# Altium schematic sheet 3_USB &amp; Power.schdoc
size 309 x 223 mm; Symbol: Sheet-Symbol_A4; Device: Sheet-Symbol_A4; Company: EasyEDA.com; Drawed: EasyEDA Pro; Reviewed: EasyEDA Pro; Version: V0.1; Page Size: A4; @Project Name: Recovery-Board-Kaveet-Saksham-Edition; @Page Count: 3; @Update Date: 2023-08-21; @Create Date: 2023-08-02; @Schematic Name: Schematic; Part Number: JLCPCB-002; @Page No: 3; @Page Name: USB &amp; Power
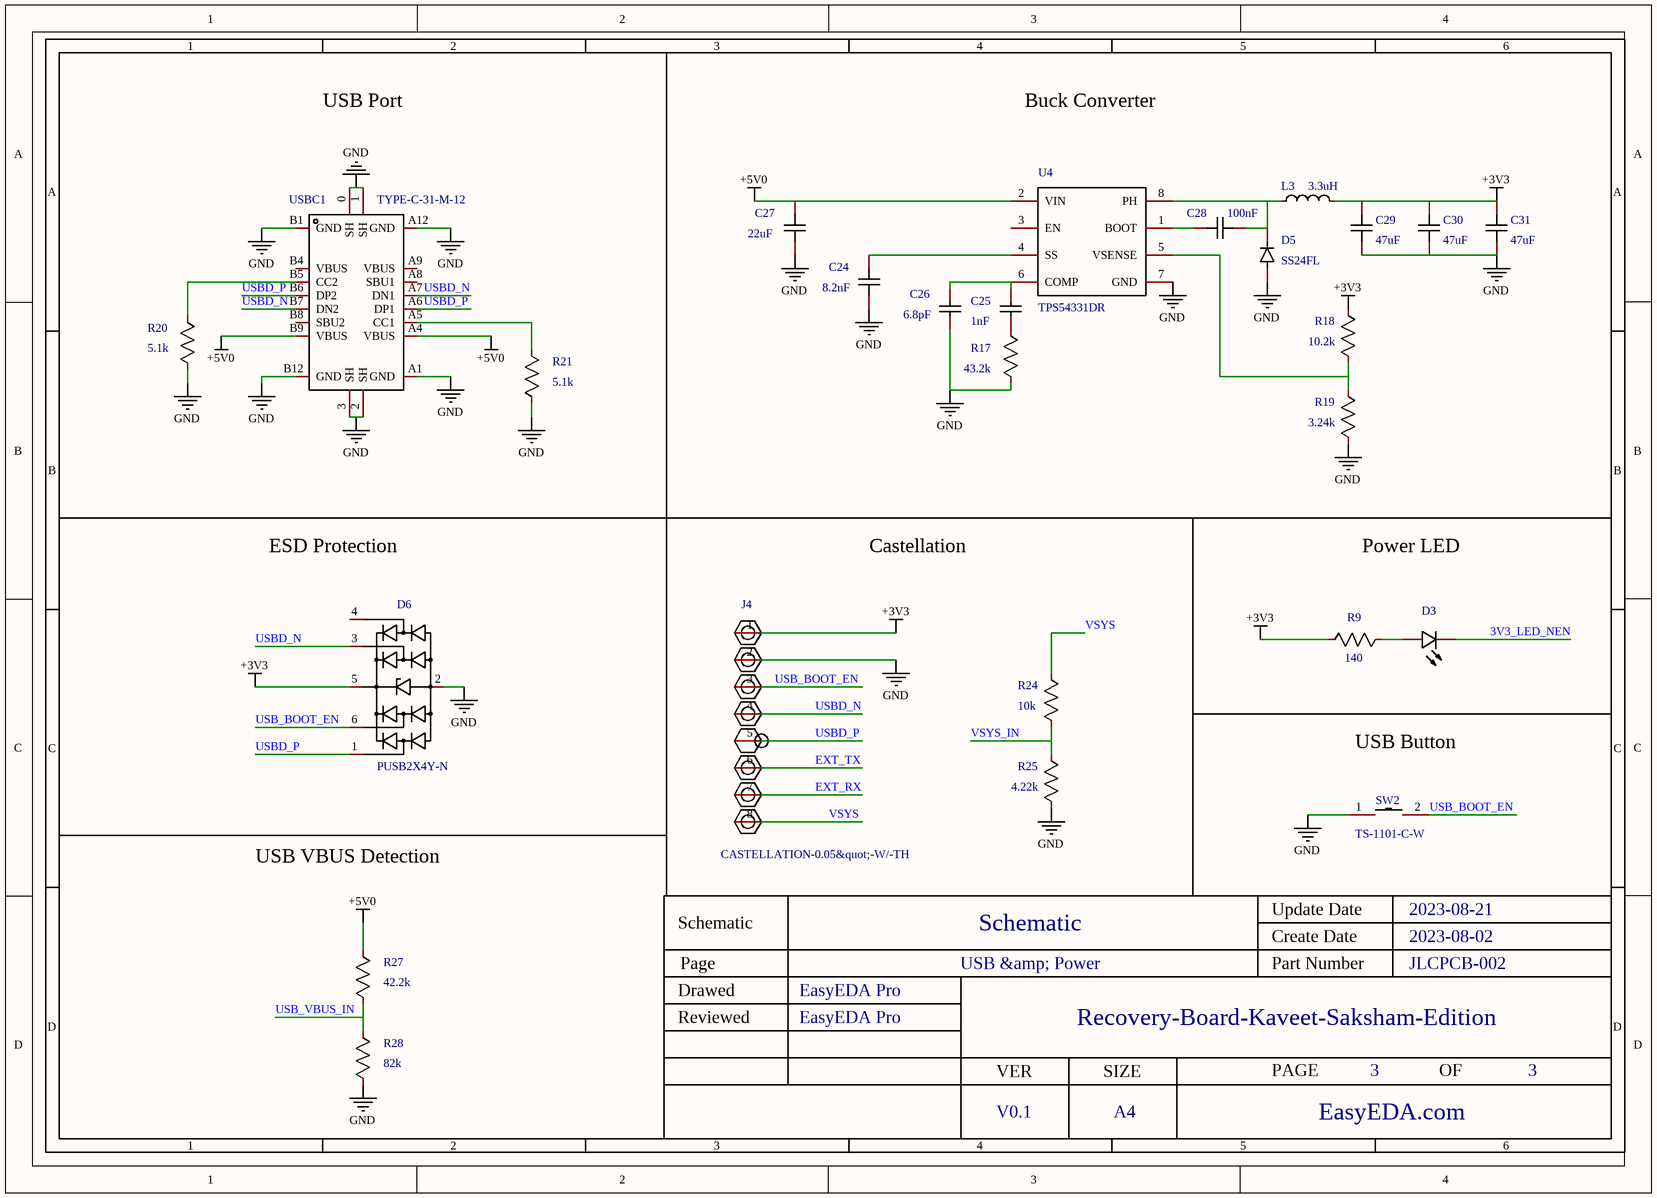
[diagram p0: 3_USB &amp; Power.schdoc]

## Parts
C24  8.2nF  [C0603]
C25  1nF  [C0402]
C26  6.8pF  [C0603]
C27  22uF  [C1210]
C28  100nF  [C0402]
C29  47uF  [C1206]
C30  47uF  [C1206]
C31  47uF  [C1206]
D3  16-213/SDRC/S530-A3/TR8  (value not drawn)
D5  SS24FL  [SODFL3617X108N]
D6  PUSB2X4Y-N  [SOT-363_L2.1-W1.3-P0.65-LS2.3-BL]
J4  CASTELLATION-0.05&quot;-W/-TH  [CASTELLATION-0.05"-W/-TH]
L3  3.3uH  [IND-SMD_L7.3-W6.6]
R9  140
R17  43.2k
R18  10.2k
R19  3.24k
R20  5.1k
R21  5.1k
R24  10k
R25  4.22k
R27  42.2k
R28  82k
SW2  TS-1101-C-W  [SW-SMD_L6.0-W3.3-LS8.0]
U4  TPS54331DR  [SOIC-8_L5.0-W4.0-P1.27-LS6.0-BL]
USBC1  TYPE-C-31-M-12  [USB-C_SMD-TYPE-C-31-M-12]

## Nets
+3V3: C29.2 C30.2 C31.2 D6.5(VCC) J4.1 L3.2 R9.1 R18.2
+5V0: C27.2 R27.2 U4.2(VIN) USBC1.A4(VBUS) USBC1.B9(VBUS)
GND: C24.1 C26.1 C27.1 C29.1 C30.1 C31.1 D5.A D6.2(GND) J4.2 R17.1 R19.1 R20.1 R21.1 R25.1 R28.1 SW2.1 U4.7(GND) USBC1.0(SH) USBC1.1(SH) USBC1.2(SH) USBC1.3(SH) USBC1.A1(GND) USBC1.A12(GND) USBC1.B1(GND) USBC1.B12(GND)
3V3_LED_NEN: D3.1(-)
EXT_RX: J4.7
EXT_TX: J4.6
USB_BOOT_EN: D6.6 J4.3 SW2.2
USB_VBUS_IN: R27.1 R28.2
USBD_N: D6.3 J4.4 USBC1.A7(DN1) USBC1.B7(DN2)
USBD_P: D6.1 J4.5 USBC1.A6(DP1) USBC1.B6(DP2)
VSYS: J4.8 R24.2
VSYS_IN: R24.1 R25.2
NetC24_2: C24.2 U4.4(SS)
NetC25_1: C25.1 R17.2
NetC25_2: C25.2 C26.2 U4.6(COMP)
NetC28_1: C28.1 U4.1(BOOT)
NetC28_2: C28.2 D5.C L3.1 U4.8(PH)
NetD3_2: D3.2(+) R9.2
NetR18_1: R18.1 R19.2 U4.5(VSENSE)
NetR20_2: R20.2 USBC1.B5(CC2)
NetR21_2: R21.2 USBC1.A5(CC1)

Not connected (* = marked no-connect by the designer): D6 4; U4 3(EN); USBC1 A8(SBU1) A9(VBUS) B4(VBUS) B8(SBU2)

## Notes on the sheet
- USB Port
- Buck Converter
- ESD Protection
- Castellation
- Power LED
- USB Button
- USB VBUS Detection

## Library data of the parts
C24 = CC0603KRX7R9BB822: Capacitance: Tolerance:±10% Tolerance:±10% Voltage Rated: Temperature Coefficient:; Manufacturer: YAGEO(国巨); Add into BOM: yes; Tolerance: ±10%
C25 = 0402B102K500NT: Capacitance: Tolerance:±10% Tolerance:±10% Voltage Rated: Temperature Coefficient:; Manufacturer: FH(风华); Add into BOM: yes; Tolerance: ±10%
C26 = 0603CG6R8C500NT: Capacitance: Voltage Rated: Temperature Coefficient:; Manufacturer: FH(风华); Add into BOM: yes
C27 = GCM32ER71C226KE19L: Capacitance: Tolerance:±10% Tolerance:±10% Voltage Rated: Temperature Coefficient:; Manufacturer: muRata(村田); Add into BOM: yes; Tolerance: ±10%
C28 = V104K0402X5R250NBT: Capacitance: Tolerance:±10% Tolerance:±10% Voltage Rated: Temperature Coefficient:; Manufacturer: VIIYONG(微容); Add into BOM: yes; Tolerance: ±10%
C29-C31 = CL31A476MPHNNNE: Capacitance: Tolerance:±20% Tolerance:±20% Voltage Rated: Temperature Coefficient:; Manufacturer: SAMSUNG(三星); Add into BOM: yes; Tolerance: ±20%
D3 = 16-213SDRC/S530-A3/TR8: Manufacturer: EVERLIGHT(亿光); Convert to PCB: yes; Origin Footprint: LED0402-RD
D5 = SS24FL: Convert to PCB: yes
D6 = PUSB2X4Y-N: Manufacturer: BORN(伯恩半导体); Add into BOM: yes
J4 = CASTELLATION-0.05"-W/-TH: Convert to PCB: yes
L3 = YSPI0730-3R3M: Inductance: Tolerance:±20% Tolerance:±20% Rated Current: DC Resistance (DCR):; Manufacturer: YJYCOIN(益嘉源); Add into BOM: yes; Tolerance: ±20%
R9 = MCR03EZPFX1400: Convert to PCB: yes; Origin Footprint: R0603
R17 = RC0603FR-0710RL: Manufacturer Part: 0402WGF4322TCE; Symbol: 10; Convert to PCB: yes; Origin Footprint: R0603
R18 = RC0603FR-0710RL: Manufacturer Part: RMC040210.2K1%N; Symbol: 10; Convert to PCB: yes; Origin Footprint: R0603
R19 = RC0603FR-0710RL: Manufacturer Part: 0402WGF3241TCE; Symbol: 10; Convert to PCB: yes; Origin Footprint: R0603
R20 R21 = MCR03EZPFX1400: Manufacturer Part: RC0402JR-075K1L; Symbol: 140; Convert to PCB: yes; Origin Footprint: R0603
R24 = RC0603FR-0710RL: Manufacturer Part: TR0402D10KQ1025; Symbol: 10; Convert to PCB: yes; Origin Footprint: R0603
R25 = RC0603FR-0710RL: Manufacturer Part: RT0402BRD074K22L; Symbol: 10; Convert to PCB: yes
R27 = RC0603FR-0710RL: Manufacturer Part: RC0402FR-0742K2L; Symbol: 10; Convert to PCB: yes; Origin Footprint: R0603
R28 = RC0603FR-0710RL: Manufacturer Part: 0402WGF8202TCE; Symbol: 10; Convert to PCB: yes
SW2 = TS-1101-C-W: Contact Current:50mA Voltage Rating (AC):- Voltage Rating (DC):12V Power Rating:- Insulation Resistance:- Circuit:SPST Mounting Style:Brick nogging Actuator Style:Rectangle button Actuator/Cap Color:白色带淡绿 With Lamp:No Operating Force:260gf Mechanical Life; Manufacturer: XKB Connectivity(中国星坤); Add into BOM: yes; Contact Current: 50mA; Voltage Rating (DC): 12V; Circuit: SPST; Actuator/Cap Color: 白色带淡绿; With Lamp: No; Operating Force: 260gf; Mechanical Life: 50000次; Switch Length: 6mm; Switch Width: 3.6mm; Switch Height: 2.5mm
U4 = TPS54331DR: Function:Step-down type Synchronous Rectification:NO Output Type:Adjustable Number of Outputs:1 Topology:Step-down Input Voltage:3.5V~28V Input Voltage:3.5V~28V Output Voltage:0.8V~25V Output Voltage:0.8V~25V Output Current (Max):3A Switching Frequency:57; Manufacturer: TI(德州仪器); Add into BOM: yes; Synchronous Rectification: NO; Number of Outputs: 1; Output Current (Max): 3A; Switching Frequency: 570kHz
USBC1 = TYPE-C-31-M-12: Connector Type:Type-C Standard:- Gender:Female Number of Contacts:16P Number of Ports:1 Mounting Style:- Current Rating - Power (Max):5A Contact Material:- Contact Plating:- Operating Temperature Range:- Operating Temperature Range:- Welding Temperature (; Manufacturer: 韩国韩荣; Add into BOM: yes; Connector Type: Type-C; Gender: Female; Number of Contacts: 16P; Number of Ports: 1; Current Rating - Power (Max): 5A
